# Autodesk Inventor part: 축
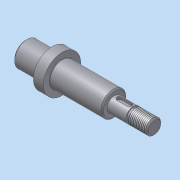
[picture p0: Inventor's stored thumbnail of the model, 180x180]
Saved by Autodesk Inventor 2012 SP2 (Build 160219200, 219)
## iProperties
Created: 2015-03
Part Number: 축
Material: 강
Document SubType Name: Modeling
Designer: KYOUNG IL JANG
Density: 1 g/cm^3
CustomPartVersion: 1
Author: KYOUNG IL JANG
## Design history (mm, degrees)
sketch "스케치5"
  geometry: L1 (0, 0)-(103, 0); L2 (0, 0)-(103, 0); L3 (103, 0)-(103, 6); L4 (71, 6)-(71, 10); L5 (71, 10)-(29, 10); L6 (29, 10)-(29, 15); L7 (29, 15)-(21, 15); L8 (21, 15)-(21, 10); L9 (21, 10)-(0, 10); L10 (0, 10)-(0, 0); L11 (86, 6)-(86, 5); L12 (86, 5)-(88, 5); L13 (88, 5)-(88, 6); L14 (103, 6)-(88, 6); L15 (86, 6)-(71, 6)
  constraints: 31 end point, 12 perpendicular, 9 parallel, 1 collinear, 1 horizontal
  dimensions: "d43" = 20 diameter of L9 L1; "d44" = 30 diameter of L7 L1; "d45" = 20 diameter of L5 L2; "d47" = 8 distance of L6.end L7.end; "d48" = 32 distance between parallel lines of L3 L4; "d49" = 42 distance between parallel lines of L4 L6; "d50" = 21 distance of L8.end L9.end; "d52" = 12 diameter of L14 L1; "d53" = 15 distance between parallel lines of L3 L13; "d54" = 2 distance of L11.end L12.end; "d55" = 1 distance between parallel lines of L14 L12
revolve "회전4" sketch "스케치5" stored, may be unused: angle "d51" = 90 deg
feature "스레드6" dims "d56" = 10, "d57" = 0
chamfer "모따기6" distance "d32" = 1; stored, may be unused: second distance "d33" = 0.4, angle "d34" = 45 deg
chamfer "모따기5" distance "d27" = 1; stored, may be unused: second distance "d28" = 0.125, angle "d29" = 45 deg
fillet "모깎기1" dims "d17" = 0.3
fillet "모깎기2" dims "d18" = 0.3
chamfer "모따기3" distance "d19" = 1; stored, may be unused: second distance "d20" = 1, angle "d21" = 45 deg
node "작업 평면1"
sketch "스케치6"
  geometry: L1 (-3.5, 2)-(4.5, 2); L2 (4.5, -2)-(-3.5, -2); L3 (-7.5, 9)-(-7.5, -9) reference; A1 r 2 centre (4.5, 0) between (4.5, -2) and (4.5, 2); A2 r 2 centre (-3.5, 0) between (-3.5, 2) and (-3.5, -2); 1 further point
  constraints: 4 end point, 4 point on circle, 4 tangent, 2 centre point, 1 horizontal, 1 horizontal alignment, 1 parallel
  dimensions: "d59" = 2 distance edge to line of A2 L3; "d60" = 12 dimension on A1 A2; "d61" = 4 distance between parallel lines of L2 L1
extrude "돌출1" cut sketch "스케치6" distance "d62" = 2.3; taper "d63" = 0 deg
node "솔리드1"
node "솔리드2"
other parameters: "d46" = 12
